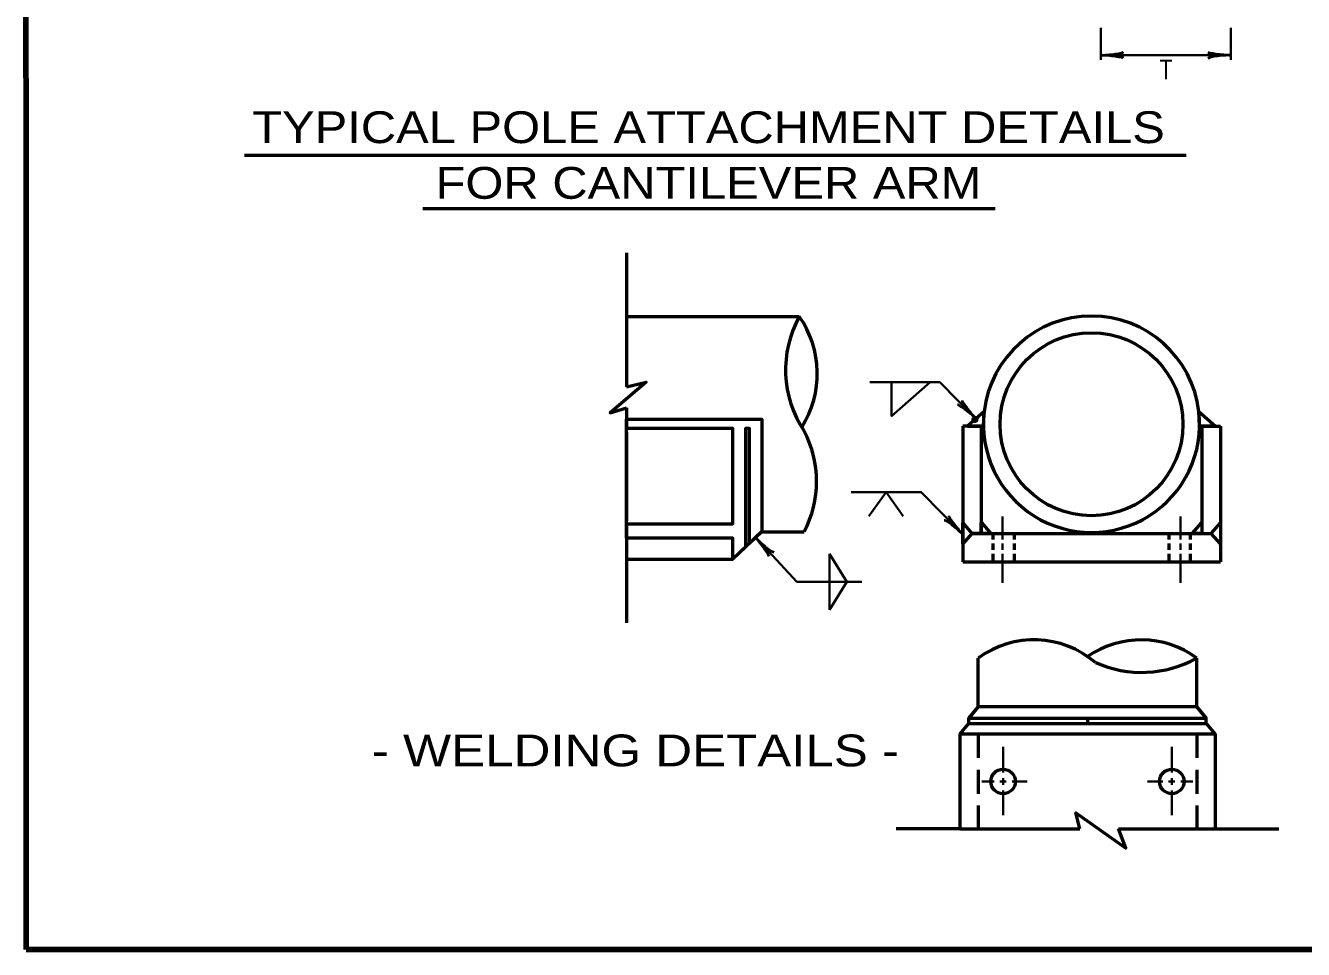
# Model space of a CAD drawing. Extents: x -274 to 582, y -298 to 246.
# Drawn here: x -216.4 to -23.4, y -286.1 to -146.7 of the extents above; entities that cross this region are included whole.
import ezdxf
from ezdxf.enums import TextEntityAlignment as Align

# ---------------------------------------------------------------- set-up
doc = ezdxf.new("R2010")
doc.units = 0
doc.header["$LTSCALE"] = 1.2
doc.header["$PDMODE"] = 32
doc.header["$PDSIZE"] = 0.6
doc.linetypes.add('MEDIUM_DASHED', pattern=[4.5, 3, -1.5])
doc.layers.add('1', color=7, linetype='Continuous', lineweight=53)

msp = doc.modelspace()

# ---------------------------------------------------------------- linework, layer by layer
at = {"layer": '1', "lineweight": 35}
for p, q in [((-54.054, -147.076), (-54.054, -151.904)), ((-34.424, -147.076), (-34.424, -151.904)), ((-54.054, -151.184), (-34.424, -151.184)), ((-86.46, -217.124), (-89.048, -220.778)), ((-86.46, -217.124), (-83.872, -220.778)), ((-68.88, -220.808), (-68.88, -224.272)), ((-42.008, -220.808), (-42.008, -224.272)), ((-68.88, -224.9), (-68.88, -225.836)), ((-42.008, -224.9), (-42.008, -225.836)), ((-95.03, -230.654), (-95.03, -226.418)), ((-95.03, -226.418), (-92.4, -230.654)), ((-68.88, -226.464), (-68.88, -230.8)), ((-42.008, -226.464), (-42.008, -230.8)), ((-95.03, -230.654), (-95.03, -234.89)), ((-95.03, -234.89), (-92.4, -230.654)), ((-68.798, -255.578), (-68.798, -259.428)), ((-43.318, -255.578), (-43.318, -259.428)), ((-68.798, -260.316), (-68.798, -261.276)), ((-43.318, -260.316), (-43.318, -261.276)), ((-71.994, -260.796), (-70.166, -260.796)), ((-69.278, -260.796), (-68.318, -260.796)), ((-68.798, -262.164), (-68.798, -265.868)), ((-67.43, -260.796), (-65.14, -260.796)), ((-44.686, -260.796), (-46.976, -260.796)), ((-42.838, -260.796), (-43.798, -260.796)), ((-43.318, -262.164), (-43.318, -265.868)), ((-40.122, -260.796), (-41.95, -260.796))]:
    msp.add_line(p, q, dxfattribs=at)
at = {"layer": '1'}
for p, q in [((-183.342, -166.259), (-41.155, -166.259)), ((-156.395, -174.346), (-69.996, -174.346)), ((-125.66, -181.026), (-125.66, -201.242)), ((-125.66, -190.626), (-99.572, -190.626)), ((-125.66, -204.428), (-125.66, -207.524)), ((-125.66, -206.547), (-125.66, -207.21)), ((-125.66, -221.936), (-125.66, -207.524)), ((-125.66, -208.137), (-125.66, -221.455)), ((-72.088, -207.168), (-74.898, -207.168)), ((-72.088, -207.168), (-72.088, -223.348)), ((-38.8, -207.168), (-35.99, -207.168)), ((-40.248, -223.348), (-38.81, -221.722)), ((-125.66, -222.416), (-125.66, -223.741)), ((-105.204, -223.093), (-109.594, -227.241)), ((-105.204, -223.096), (-98.838, -223.096)), ((-73.526, -223.348), (-38.8, -223.348)), ((-70.324, -223.348), (-70.324, -224.272)), ((-70.324, -223.456), (-70.324, -224.272)), ((-67.114, -223.348), (-67.114, -224.272)), ((-67.114, -223.376), (-67.114, -224.272)), ((-43.774, -223.348), (-43.774, -224.104)), ((-43.774, -223.376), (-43.774, -224.272)), ((-40.564, -223.348), (-40.564, -224.272)), ((-70.324, -224.9), (-70.324, -225.836)), ((-67.114, -224.9), (-67.114, -225.836)), ((-43.774, -224.9), (-43.774, -225.836)), ((-40.564, -224.9), (-40.564, -225.836)), ((-125.66, -227.238), (-109.594, -227.238)), ((-74.898, -227.628), (-35.99, -227.628)), ((-70.324, -226.464), (-70.324, -227.628)), ((-70.324, -226.464), (-70.324, -227.628)), ((-67.114, -226.464), (-67.114, -227.628)), ((-67.114, -226.588), (-67.114, -227.628)), ((-43.774, -226.464), (-43.774, -227.628)), ((-43.774, -226.758), (-43.774, -227.628)), ((-40.564, -226.464), (-40.564, -227.628)), ((-40.564, -227.026), (-40.564, -227.628)), ((-72.554, -249.534), (-72.554, -242.174)), ((-39.564, -249.534), (-39.564, -242.174)), ((-73.974, -251.23), (-72.554, -249.534)), ((-39.564, -249.534), (-38.142, -251.23)), ((-75.332, -253.642), (-73.974, -252.04)), ((-73.974, -252.04), (-73.974, -251.23)), ((-56.058, -251.23), (-56.058, -252.04)), ((-38.142, -252.04), (-38.142, -251.23)), ((-38.142, -252.04), (-36.786, -253.642)), ((-75.332, -253.642), (-75.332, -267.948)), ((-36.786, -253.642), (-36.786, -267.948)), ((-75.332, -267.948), (-84.966, -267.948)), ((-75.332, -267.948), (-57.198, -267.948)), ((-51.38, -267.948), (-36.786, -267.948)), ((-36.784, -267.948), (-27.15, -267.948))]:
    msp.add_line(p, q, dxfattribs=at)
at = {"layer": '1', "linetype": 'MEDIUM_DASHED'}
for p, q in [((-72.554, -253.642), (-72.554, -267.948)), ((-39.564, -253.642), (-39.564, -267.948))]:
    msp.add_line(p, q, dxfattribs=at)
at = {"layer": '1', "lineweight": 158}
msp.add_line((575.293, -286.139), (-216.307, -286.139), dxfattribs=at)
msp.add_lwpolyline([(575.293, 239.961), (-216.407, 239.861), (-216.307, -286.139)], dxfattribs=at)
at = {"layer": '1'}
for points in [[(-125.66, -201.242), (-122.71, -200.526), (-128.12, -205.148), (-125.66, -204.428)], [(-125.66, -206.116), (-105.204, -206.116), (-105.204, -223.096), (-107.11, -224.896)], [(-107.11, -224.894), (-107.11, -207.524), (-107.69, -207.524), (-107.69, -225.442), (-109.594, -227.238), (-109.594, -224.09), (-125.66, -224.09), (-125.66, -221.936), (-109.594, -221.936), (-109.594, -207.524), (-125.66, -207.524), (-125.66, -206.116)], [(-74.898, -207.168), (-74.898, -224.948), (-74.898, -227.628)], [(-38.8, -207.168), (-38.8, -223.348), (-37.362, -223.348)], [(-35.99, -207.168), (-35.99, -224.948), (-35.99, -227.628)], [(-72.078, -221.722), (-70.64, -223.348), (-73.526, -223.348)], [(-72.088, -223.348), (-72.088, -221.71), (-72.078, -221.722)], [(-38.8, -221.71), (-38.8, -223.348), (-40.248, -223.348)], [(-125.66, -221.936), (-125.66, -227.238), (-125.66, -236.838)], [(-57.198, -267.948), (-57.792, -265.502), (-50.26, -270.872), (-51.38, -267.948)]]:
    msp.add_lwpolyline(points, dxfattribs=at)
at = {"layer": '1', "lineweight": 35}
for points in [[(-72.908, -206.07), (-78.344, -200.552), (-88.894, -200.552)], [(-85.622, -200.552), (-85.622, -205.658), (-79.82, -200.552)], [(-74.898, -223.506), (-81.186, -217.124), (-91.736, -217.124)], [(-106.156, -223.996), (-99.94, -230.654), (-90.12, -230.654)]]:
    msp.add_lwpolyline(points, dxfattribs=at)
at = {"layer": '1'}
for points in [[(-71.664, -204.97), (-74.152, -207.168), (-71.774, -207.168)], [(-39.224, -204.97), (-36.736, -207.168), (-39.114, -207.168)], [(-74.898, -224.948), (-74.898, -221.748), (-73.526, -223.348)], [(-37.362, -223.348), (-35.99, -221.748), (-35.99, -224.948)], [(-39.564, -249.534), (-72.554, -249.534), (-73.974, -251.23), (-38.142, -251.23)], [(-75.332, -253.642), (-73.974, -252.04), (-38.142, -252.04), (-36.786, -253.642)]]:
    msp.add_lwpolyline(points, close=True, dxfattribs=at)
for centre, radius in [((-55.445, -206.887), 13.806), ((-68.798, -260.796), 1.849), ((-43.318, -260.796), 1.849)]:
    msp.add_circle(centre, radius, dxfattribs=at)
for centre, radius, start, end in [((-84.99, -198.679), 16.658, 151.08959, 213.71646), ((-111.849, -199.24), 14.998, 327.41459, 35.05644), ((-55.444, -206.887), 16.332, 6.74279, 173.25721), ((-55.444, -206.887), 16.332, 173.25721, 6.74279), ((-113.101, -215.518), 16.151, 332.02028, 28.04015), ((-64.12, -253.742), 14.316, 49.69817, 126.09413), ((-47.977, -253.675), 14.25, 53.8173, 124.45264), ((-47.859, -227.266), 17.06, 245.77277, 299.09384)]:
    msp.add_arc(centre, radius, start, end, dxfattribs=at)
at = {"layer": '1', "lineweight": 40}
for centre, major_axis, ratio, start_param, end_param in [((-52.745, -150.853), (-2.143, -0.187), 0.122415, 0.8963533, 3.1415927), ((-52.709, -151.438), (-2.108, 0.211), 0.07063, 3.1407148, 5.41811), ((-35.734, -151.516), (2.143, 0.187), 0.122415, 0.8963533, 3.1415927), ((-35.734, -151.516), (2.143, 0.187), 0.122415, 0.8963533, 3.1415927), ((-35.769, -150.93), (2.108, -0.211), 0.07063, 3.1407148, 5.41811), ((-35.769, -150.93), (2.108, -0.211), 0.07063, 3.1407148, 5.41811), ((-74.063, -205.37), (1.637, -1.395), 0.122415, 0.8963533, 3.1415927), ((-73.671, -204.934), (1.329, -1.649), 0.07063, 3.1407148, 5.41811), ((-76.053, -222.806), (1.637, -1.395), 0.122415, 0.8963533, 3.1415927), ((-76.053, -222.806), (1.637, -1.395), 0.122415, 0.8963533, 3.1415927), ((-75.661, -222.37), (1.329, -1.649), 0.07063, 3.1407148, 5.41811), ((-75.661, -222.37), (1.329, -1.649), 0.07063, 3.1407148, 5.41811), ((-105.424, -225.152), (-1.284, 1.685), 0.07063, 3.1407148, 5.41811), ((-105.424, -225.152), (-1.284, 1.685), 0.07063, 3.1407148, 5.41811), ((-105.02, -224.727), (-1.599, 1.438), 0.122415, 0.8963533, 3.1415927), ((-105.02, -224.727), (-1.599, 1.438), 0.122415, 0.8963533, 3.1415927)]:
    msp.add_ellipse(centre, major_axis=major_axis, ratio=ratio, start_param=start_param, end_param=end_param, dxfattribs=at)
at = {"layer": '1'}
msp.add_point((-73.014, -206.158), dxfattribs=at)

# ---------------------------------------------------------------- texts
for s, height, width, p in [('T', 3, 0.8, (-44.174, -154.857)), ('TYPICAL POLE ATTACHMENT DETAILS', 4.8, 1.15, (-113.28, -164.459)), ('FOR CANTILEVER ARM', 4.8, 1.15, (-113.28, -172.859)), ('- WELDING DETAILS -', 4.8, 1.2, (-124.313, -258.511))]:
    msp.add_text(s, height=height, dxfattribs=dict(at, width=width)).set_placement(p, align=Align.CENTER)

doc.saveas('drawing.dxf')
